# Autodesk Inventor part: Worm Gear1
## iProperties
Created: 2011-05
Part Number: Worm Gear1
Material: Steel, Mild
Document SubType Name: Modeling
Designer: 904Chiaki
Categories: <?xml version="1.0" encoding="UTF-16"?> <MemberInstance><Categories><FamilyTemplate><FamilyTemplateParameter ValueType="xs:double" Id="1" ObjectReferenceKey="da
Density: 7.86 g/cm^3
Mass: 36271.6 g
Surface Area: 4778.59 cm^2
Volume: 4614.7 cm^3
CustomPartVersion: 1
Author: 904Chiaki
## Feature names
1. Base Body [Revolution]
2. Base Body2 [Revolution]
3. Tooth [Revolution]
4. Tooth Pattern [Circular Pattern]
5. Extrusion1
6. Mirror1
7. Extrusion2
8. Extrusion3
9. Fillet3
10. Extrusion4
11. Extrusion5
12. Chamfer2
13. Fillet4
